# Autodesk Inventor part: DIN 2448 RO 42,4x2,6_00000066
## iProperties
Created: 2006-03
Part Number: DIN 2448 RO 42,4x2,6_00000066
Material: Default
Document SubType Name: Modeling
Designer: Carlo
Stock Number: DIN 2448 RO 42,4x2,6
Mass: 577.032 g
Surface Area: 4452.08 cm^2
Volume: 577.032 cm^3
Density: 1 g/cm^3
G_L: 1805.000 mm
G_W: 42.400 mm
G_H: 42.400 mm
AFG_Item: 42.4 x 2.6
CSToolsMass: 1.0
CSToolsVolume: 577032.0
CSToolsArea: 4452.0
Author: Carlo
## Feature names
1. AFG_Detailed_DIN 2448 RO 42,4x2,6_00000066 [Extrusion]
2. AFG_Simplified_DIN 2448 RO 42,4x2,6_00000066 [Extrusion]
3. AFG_StartExtrusion_1 [Extrusion]
4. AFG_StartExtrusion_2 [Extrusion]
5. AFG_EndExtrusion_1 [Extrusion]
6. AFG_EndExtrusion_2 [Extrusion]
